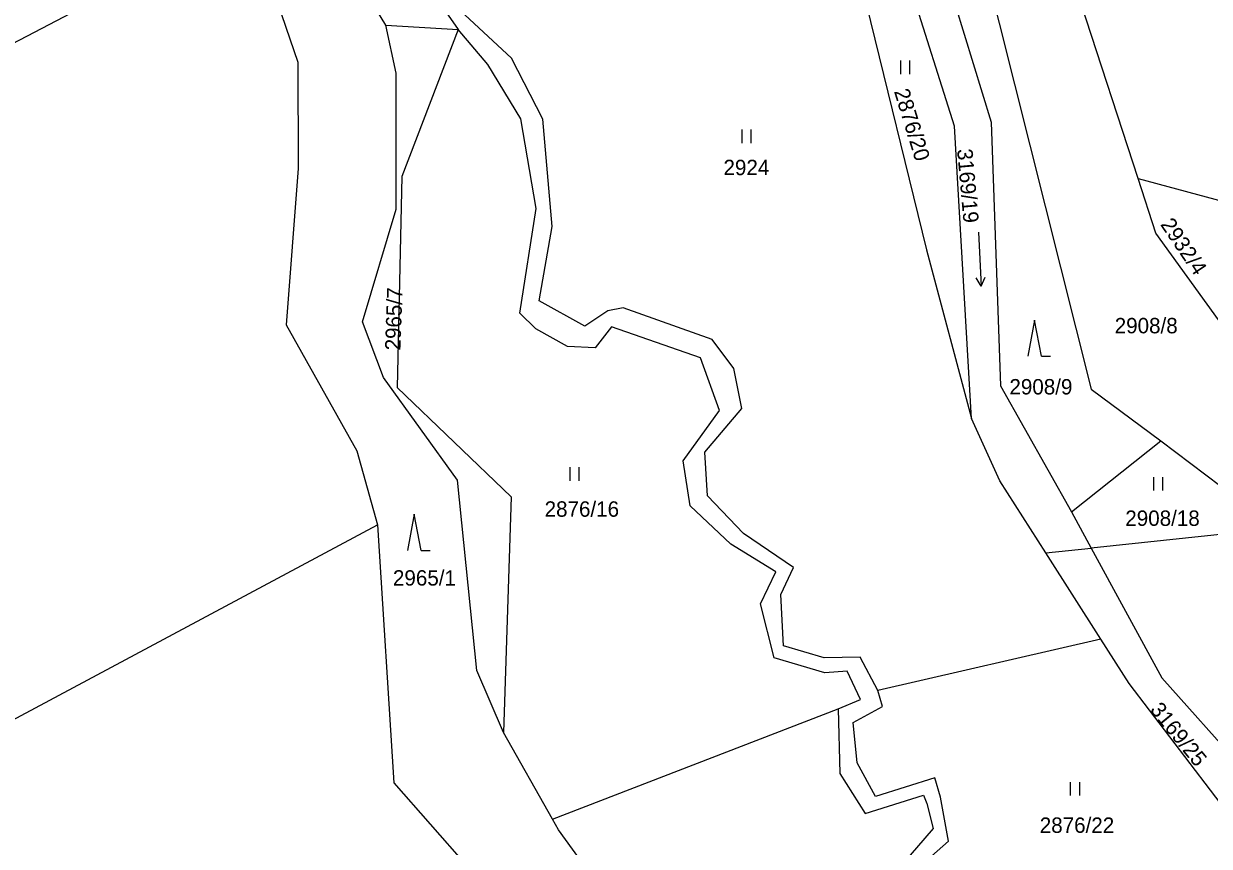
# Model space of a CAD drawing. Extents: x -776734 to -748832, y -1118122 to -976986.
# Drawn here: x -754304.9 to -754174.1, y -1114095.9 to -1114005.1 of the extents above; entities that cross this region are included whole.
import ezdxf

# ---------------------------------------------------------------- set-up
doc = ezdxf.new("R2010")
doc.units = 0
for name, color, linetype in [('KM_Hranice parcel', 7, 'Continuous'), ('KM_Parcelní čísla', 7, 'Continuous'), ('KM_Značky kultur', 7, 'Continuous')]:
    doc.layers.add(name, color=color, linetype=linetype)

msp = doc.modelspace()

# ---------------------------------------------------------------- linework, layer by layer
at = {"layer": 'KM_Hranice parcel'}
for p, q in [((-754426.25, -1114069.99), (-754280.05, -1113993.61)), ((-754259.2, -1114002.56), (-754257, -1114005.73)), ((-754181.94, -1114022.18), (-754188.22, -1114002.88)), ((-754264.97, -1114005.24), (-754257, -1114005.73)), ((-754181.94, -1114022.18), (-754170.88, -1114025.15)), ((-754189.3, -1114058.98), (-754179.42, -1114051.13)), ((-754179.42, -1114051.13), (-754166.63, -1114060.81)), ((-754189.3, -1114058.98), (-754187.12, -1114062.98)), ((-754394.86, -1114129.35), (-754265.87, -1114060.4)), ((-754166.63, -1114060.81), (-754187.12, -1114062.98)), ((-754192.11, -1114063.51), (-754187.12, -1114062.98)), ((-754186.05, -1114073.02), (-754192.11, -1114063.51)), ((-754186.05, -1114073.02), (-754210.68, -1114078.71)), ((-754246.56, -1114092.91), (-754215.05, -1114080.73)), ((-754246.56, -1114092.91), (-754251.99, -1114083.32))]:
    msp.add_line(p, q, dxfattribs=at)
for points in [[(-754264.97, -1114005.24), (-754271.25, -1113994.86), (-754268.32, -1113981.1)], [(-754280.05, -1113993.61), (-754274.67, -1114009.32), (-754274.63, -1114021.06), (-754275.96, -1114038.32), (-754268.16, -1114052.24), (-754265.87, -1114060.4)], [(-754198.97, -1113998.24), (-754187.1, -1114045.44), (-754179.42, -1114051.13)], [(-754203.13, -1113999.73), (-754198.15, -1114015.96), (-754197.14, -1114045.06), (-754189.3, -1114058.98)], [(-754207.02, -1114001.12), (-754211.95, -1114002.88), (-754205.31, -1114030.05), (-754200.31, -1114048.68)], [(-754200.31, -1114048.68), (-754202.19, -1114016.38), (-754207.02, -1114001.12)], [(-754210.68, -1114078.71), (-754212.61, -1114075.03), (-754216.57, -1114075.07), (-754221.08, -1114073.76), (-754221.38, -1114068.08), (-754219.96, -1114065.11), (-754225.49, -1114061.37), (-754229.48, -1114057.19), (-754229.74, -1114052.37), (-754225.66, -1114047.55), (-754226.55, -1114043.15), (-754228.94, -1114039.93), (-754238.78, -1114036.46), (-754240.45, -1114036.76), (-754242.99, -1114038.47), (-754248.04, -1114035.66), (-754246.62, -1114027.45), (-754247.65, -1114015.62), (-754251.11, -1114008.9), (-754256.23, -1114004.11), (-754259.2, -1114002.56)], [(-754251.99, -1114083.32), (-754254.91, -1114076.48), (-754257.06, -1114055.48), (-754265.23, -1114044.14), (-754267.54, -1114038), (-754263.83, -1114025.56), (-754263.83, -1114010.53), (-754264.97, -1114005.24)], [(-754257, -1114005.73), (-754263.21, -1114021.94), (-754263.73, -1114045.24), (-754251.12, -1114057.32), (-754251.99, -1114083.32)], [(-754215.05, -1114080.73), (-754212.58, -1114079.68), (-754214.06, -1114076.56), (-754216.51, -1114076.75), (-754222.12, -1114075.08), (-754223.62, -1114069.14), (-754221.91, -1114065.58), (-754226.89, -1114062.54), (-754231.39, -1114058.31), (-754232.16, -1114053.34), (-754228.15, -1114047.77), (-754230.24, -1114041.96), (-754240.07, -1114038.55), (-754241.85, -1114040.87), (-754244.93, -1114040.71), (-754248.41, -1114038.75), (-754250.19, -1114037.03), (-754248.37, -1114025.48), (-754250.06, -1114015.58), (-754253.71, -1114009.57), (-754257, -1114005.73)], [(-754170.86, -1114040.81), (-754179.98, -1114028.19), (-754181.94, -1114022.18)], [(-754192.11, -1114063.51), (-754197.18, -1114055.54), (-754200.31, -1114048.68)], [(-754265.87, -1114060.4), (-754264.1, -1114088.9), (-754244.03, -1114111.7)], [(-754187.12, -1114062.98), (-754179.33, -1114077.31), (-754161.57, -1114097.18), (-754162.14, -1114104.59)], [(-754167.2, -1114098.53), (-754182.93, -1114077.93), (-754186.05, -1114073.02)], [(-754190.62, -1114114.05), (-754189.96, -1114112.02), (-754198.28, -1114109.63), (-754196.12, -1114104.32), (-754197.62, -1114100.64), (-754202.44, -1114099.98), (-754205.36, -1114097.55), (-754202.87, -1114095.32), (-754203.76, -1114090.47), (-754204.36, -1114088.35), (-754210.92, -1114090.38), (-754212.95, -1114086.67), (-754213.4, -1114082.24), (-754210.14, -1114080.45), (-754210.68, -1114078.71)], [(-754215.05, -1114080.73), (-754214.85, -1114087.87), (-754212.07, -1114092.28), (-754205.62, -1114090.24), (-754205.26, -1114091.17), (-754204.54, -1114093.92), (-754208, -1114097.94), (-754203.75, -1114101.83), (-754199.39, -1114102.37), (-754197.98, -1114105.1), (-754199.67, -1114110.73), (-754192.92, -1114112.88), (-754193.1, -1114115.27)], [(-754218.77, -1114126.01), (-754237.42, -1114105.81), (-754245.9, -1114094.07), (-754246.56, -1114092.91)]]:
    msp.add_lwpolyline(points, dxfattribs=at)
at = {"layer": 'KM_Značky kultur'}
for p, q in [((-754208.131, -1114010.64), (-754208.131, -1114009.14)), ((-754207.13, -1114010.64), (-754207.13, -1114009.14)), ((-754225.651, -1114018.25), (-754225.651, -1114016.75)), ((-754224.65, -1114018.25), (-754224.65, -1114016.75)), ((-754199.565, -1114028.082), (-754199.251, -1114034.073)), ((-754199.251, -1114034.073), (-754199.803, -1114033.124)), ((-754199.251, -1114034.073), (-754198.801, -1114033.071)), ((-754193.36, -1114037.8), (-754194.11, -1114041.8)), ((-754192.61, -1114041.8), (-754193.36, -1114037.8)), ((-754192.61, -1114041.8), (-754191.614, -1114041.8)), ((-754244.631, -1114055.54), (-754244.631, -1114054.04)), ((-754243.63, -1114055.54), (-754243.63, -1114054.04)), ((-754180.201, -1114056.63), (-754180.201, -1114055.13)), ((-754179.2, -1114056.63), (-754179.2, -1114055.13)), ((-754261.82, -1114059.23), (-754262.57, -1114063.23)), ((-754261.07, -1114063.23), (-754261.82, -1114059.23)), ((-754261.07, -1114063.23), (-754260.074, -1114063.23)), ((-754189.381, -1114090.3), (-754189.381, -1114088.8)), ((-754188.38, -1114090.3), (-754188.38, -1114088.8))]:
    msp.add_line(p, q, dxfattribs=at)

# ---------------------------------------------------------------- texts
at = {"layer": 'KM_Parcelní čísla'}
for s, rotation, p in [('2876/20', 287, (-754208.892, -1114012.538)), ('3169/19', 275, (-754201.916, -1114018.954)), ('2932/4', 304, (-754179.534, -1114027.245)), ('2965/7', 87.999997, (-754263.36, -1114041.179)), ('3169/25', 309, (-754180.7, -1114080.854))]:
    msp.add_text(s, height=1.7, rotation=rotation, dxfattribs=at).set_placement(p)
for s, p in [('2924', (-754227.7, -1114021.8)), ('2908/8', (-754184.52, -1114039.26)), ('2908/9', (-754196.14, -1114046.01)), ('2876/16', (-754247.44, -1114059.51)), ('2908/18', (-754183.35, -1114060.52)), ('2965/1', (-754264.18, -1114067.11)), ('2876/22', (-754192.79, -1114094.41))]:
    msp.add_text(s, height=1.7, dxfattribs=at).set_placement(p)

doc.saveas('drawing.dxf')
